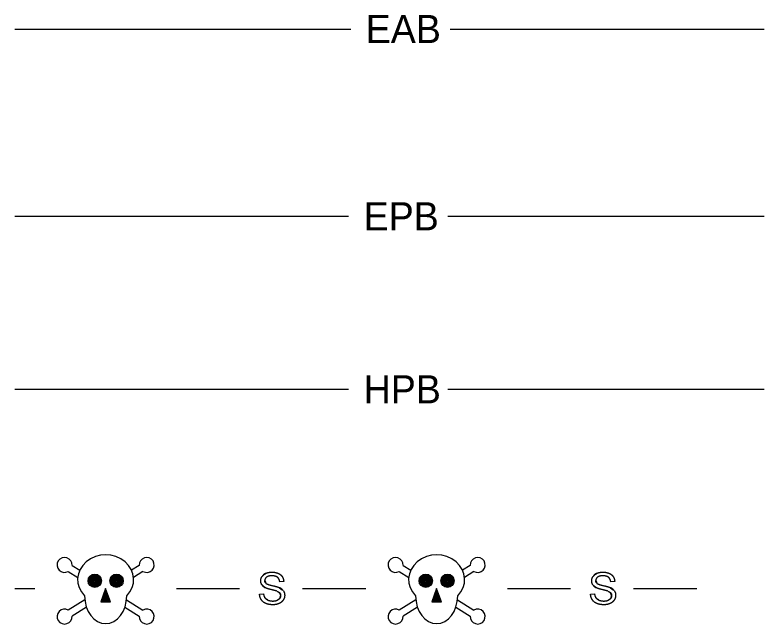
# Model space of a CAD drawing. Extents: x 754056.72 to 754059.56, y 596603.78 to 596605.61.
# Drawn here: x 754057.2575 to 754057.392, y 596604.788 to 596604.8974 of the extents above; entities that cross this region are included whole.
import ezdxf

# ---------------------------------------------------------------- set-up
doc = ezdxf.new("R2010")
doc.units = 0
doc.layers.add('Sheet_Symbology', color=7, linetype='Continuous')

msp = doc.modelspace()

# ---------------------------------------------------------------- linework, layer by layer
at = {"layer": 'Sheet_Symbology'}
for p, q in [((754057.2574689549, 596604.8949028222), (754057.3177740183, 596604.8949028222)), ((754057.3355985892, 596604.8949028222), (754057.3919940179, 596604.8949028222)), ((754057.2574689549, 596604.8612715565), (754057.3173956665, 596604.8612715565)), ((754057.3352202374, 596604.8612715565), (754057.3919940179, 596604.8612715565)), ((754057.2574689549, 596604.8302076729), (754057.3173956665, 596604.8302076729)), ((754057.3352202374, 596604.8302076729), (754057.3919940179, 596604.8302076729)), ((754057.2677177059, 596604.7985606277), (754057.2690904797, 596604.7976978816)), ((754057.2797889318, 596604.7985606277), (754057.2784161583, 596604.7976978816)), ((754057.3271609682, 596604.7985606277), (754057.3285337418, 596604.7976978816)), ((754057.3392321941, 596604.7985606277), (754057.3378594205, 596604.7976978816)), ((754057.2670463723, 596604.7974924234), (754057.2687421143, 596604.7964267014)), ((754057.2804602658, 596604.7974924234), (754057.2787645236, 596604.7964267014)), ((754057.3264896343, 596604.7974924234), (754057.3281853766, 596604.7964267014)), ((754057.3399035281, 596604.7974924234), (754057.3382077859, 596604.7964267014)), ((754057.3057381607, 596604.7956724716), (754057.305021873, 596604.7956163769)), ((754057.365181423, 596604.7956724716), (754057.3644651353, 596604.7956163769)), ((754057.2574689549, 596604.7944340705), (754057.261015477, 596604.7944340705)), ((754057.2864911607, 596604.7944340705), (754057.297813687, 596604.7944340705)), ((754057.3091362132, 596604.7944340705), (754057.3204587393, 596604.7944340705)), ((754057.3459344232, 596604.7944340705), (754057.3572569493, 596604.7944340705)), ((754057.3685794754, 596604.7944340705), (754057.3799020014, 596604.7944340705)), ((754057.273753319, 596604.794022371), (754057.273753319, 596604.794022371)), ((754057.3013972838, 596604.7934243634), (754057.3021049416, 596604.7934847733)), ((754057.3331965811, 596604.794022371), (754057.3331965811, 596604.794022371)), ((754057.3608405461, 596604.7934243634), (754057.3615482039, 596604.7934847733)), ((754057.2700067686, 596604.7924128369), (754057.2670463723, 596604.7905523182)), ((754057.2774998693, 596604.7924128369), (754057.2804602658, 596604.7905523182)), ((754057.3294500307, 596604.7924128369), (754057.3264896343, 596604.7905523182)), ((754057.3369431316, 596604.7924128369), (754057.3399035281, 596604.7905523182)), ((754057.2702921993, 596604.7911021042), (754057.2677177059, 596604.7894841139)), ((754057.2772144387, 596604.7911021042), (754057.2797889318, 596604.7894841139)), ((754057.3297354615, 596604.7911021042), (754057.3271609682, 596604.7894841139)), ((754057.3366577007, 596604.7911021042), (754057.3392321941, 596604.7894841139))]:
    msp.add_line(p, q, dxfattribs=at)
for points in [[(754057.273753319, 596604.7944340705), (754057.2728663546, 596604.7920112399), (754057.2746402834, 596604.7920112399)], [(754057.3331965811, 596604.7944340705), (754057.3323096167, 596604.7920112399), (754057.3340835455, 596604.7920112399)], [(754057.273753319, 596604.794022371), (754057.2730688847, 596604.7921527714), (754057.2744377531, 596604.7921527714)], [(754057.273753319, 596604.7936106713), (754057.273271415, 596604.792294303), (754057.2742352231, 596604.792294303)], [(754057.273753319, 596604.7931989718), (754057.2734739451, 596604.7924358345), (754057.2740326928, 596604.7924358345)], [(754057.3331965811, 596604.794022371), (754057.332512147, 596604.7921527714), (754057.3338810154, 596604.7921527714)], [(754057.3331965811, 596604.7936106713), (754057.3327146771, 596604.792294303), (754057.3336784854, 596604.792294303)], [(754057.3331965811, 596604.7931989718), (754057.3329172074, 596604.7924358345), (754057.3334759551, 596604.7924358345)], [(754057.273753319, 596604.7927872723), (754057.2736764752, 596604.7925773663), (754057.2738301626, 596604.7925773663)], [(754057.3331965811, 596604.7927872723), (754057.3331197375, 596604.7925773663), (754057.3332734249, 596604.7925773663)]]:
    msp.add_lwpolyline(points, close=True, dxfattribs=at)
for centre, radius in [((754057.2718028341, 596604.7958118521), 0.0012001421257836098), ((754057.2757038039, 596604.7958118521), 0.0012001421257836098), ((754057.3312460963, 596604.7958118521), 0.0012001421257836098), ((754057.3351470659, 596604.7958118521), 0.0012001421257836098), ((754057.2718028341, 596604.7958118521), 0.0010586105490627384), ((754057.2718028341, 596604.7958118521), 0.0009170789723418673), ((754057.2718028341, 596604.7958118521), 0.0007755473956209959), ((754057.2718028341, 596604.7958118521), 0.0006340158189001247), ((754057.2718028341, 596604.7958118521), 0.0004924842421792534), ((754057.2718028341, 596604.7958118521), 0.00035095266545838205), ((754057.2718028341, 596604.7958118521), 0.00020942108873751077), ((754057.2718028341, 596604.7958118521), 6.788951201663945e-05), ((754057.2757038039, 596604.7958118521), 0.0010586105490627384), ((754057.2757038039, 596604.7958118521), 0.0009170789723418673), ((754057.2757038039, 596604.7958118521), 0.0007755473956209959), ((754057.2757038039, 596604.7958118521), 0.0006340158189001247), ((754057.2757038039, 596604.7958118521), 0.0004924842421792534), ((754057.2757038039, 596604.7958118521), 0.00035095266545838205), ((754057.2757038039, 596604.7958118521), 0.00020942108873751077), ((754057.2757038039, 596604.7958118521), 6.788951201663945e-05), ((754057.3312460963, 596604.7958118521), 0.0010586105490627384), ((754057.3312460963, 596604.7958118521), 0.0009170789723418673), ((754057.3312460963, 596604.7958118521), 0.0007755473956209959), ((754057.3312460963, 596604.7958118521), 0.0006340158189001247), ((754057.3312460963, 596604.7958118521), 0.0004924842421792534), ((754057.3312460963, 596604.7958118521), 0.00035095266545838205), ((754057.3312460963, 596604.7958118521), 0.00020942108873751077), ((754057.3312460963, 596604.7958118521), 6.788951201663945e-05), ((754057.3351470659, 596604.7958118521), 0.0010586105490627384), ((754057.3351470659, 596604.7958118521), 0.0009170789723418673), ((754057.3351470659, 596604.7958118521), 0.0007755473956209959), ((754057.3351470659, 596604.7958118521), 0.0006340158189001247), ((754057.3351470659, 596604.7958118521), 0.0004924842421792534), ((754057.3351470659, 596604.7958118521), 0.00035095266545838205), ((754057.3351470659, 596604.7958118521), 0.00020942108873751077), ((754057.3351470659, 596604.7958118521), 6.788951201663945e-05)]:
    msp.add_circle(centre, radius, dxfattribs=at)
for centre, start, end in [((754057.2663794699, 596604.7986566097), 355.8976156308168, 299.8061705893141), ((754057.2811271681, 596604.7986566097), 240.19382941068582, 184.10238436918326), ((754057.3258227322, 596604.7986566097), 355.8976156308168, 299.8061705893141), ((754057.3405704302, 596604.7986566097), 240.19382941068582, 184.10238436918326), ((754057.2663794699, 596604.7893881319), 60.19382941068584, 4.1023843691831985), ((754057.2811271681, 596604.7893881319), 175.89761563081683, 119.80617058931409), ((754057.3258227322, 596604.7893881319), 60.19382941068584, 4.1023843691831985), ((754057.3405704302, 596604.7893881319), 175.89761563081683, 119.80617058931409)]:
    msp.add_arc(centre, 0.0013416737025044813, start, end, dxfattribs=at)
for centre, major_axis, ratio, start_param, end_param in [((754057.273753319, 596604.7960240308), (0.005031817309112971, 0), 0.8850143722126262, 5.564242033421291, 10.143721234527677), ((754057.3331965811, 596604.7960240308), (0.005031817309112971, 0), 0.8850143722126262, 5.564242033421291, 10.143721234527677), ((754057.273753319, 596604.7931432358), (-8.091779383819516e-19, -0.005031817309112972), 0.752542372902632, 4.7227348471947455, 7.843635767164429), ((754057.3331965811, 596604.7931432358), (-8.091779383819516e-19, -0.005031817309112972), 0.752542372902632, 4.7227348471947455, 7.843635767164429)]:
    msp.add_ellipse(centre, major_axis=major_axis, ratio=ratio, start_param=start_param, end_param=end_param, dxfattribs=at)
for points in [[(754057.3018525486, 596604.7966045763), (754057.3020963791, 596604.7969774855), (754057.3025646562, 596604.7971707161)], [(754057.3025646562, 596604.7971707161), (754057.3030329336, 596604.7973639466), (754057.3036056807, 596604.7973639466)], [(754057.3036056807, 596604.7973639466), (754057.3042365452, 596604.7973639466), (754057.3047183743, 596604.7971612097)], [(754057.3047183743, 596604.7971612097), (754057.3052002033, 596604.7969584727), (754057.305459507, 596604.7965645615)], [(754057.3612958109, 596604.7966045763), (754057.3615396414, 596604.7969774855), (754057.3620079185, 596604.7971707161)], [(754057.3620079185, 596604.7971707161), (754057.3624761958, 596604.7973639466), (754057.363048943, 596604.7973639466)], [(754057.363048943, 596604.7973639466), (754057.3636798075, 596604.7973639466), (754057.3641616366, 596604.7971612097)], [(754057.3641616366, 596604.7971612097), (754057.3646434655, 596604.7969584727), (754057.3649027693, 596604.7965645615)], [(754057.3016087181, 596604.7958027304), (754057.3016087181, 596604.796231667), (754057.3018525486, 596604.7966045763)], [(754057.3018076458, 596604.795097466), (754057.3016087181, 596604.7954124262), (754057.3016087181, 596604.7958027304)], [(754057.302641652, 596604.7964544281), (754057.3023293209, 596604.7962051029), (754057.3023293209, 596604.795853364)], [(754057.3023293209, 596604.795853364), (754057.3023293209, 596604.7955480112), (754057.302550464, 596604.7953508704)], [(754057.3036368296, 596604.7967037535), (754057.3029539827, 596604.7967037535), (754057.302641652, 596604.7964544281)], [(754057.3046280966, 596604.7964290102), (754057.3042925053, 596604.7967037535), (754057.3036368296, 596604.7967037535)], [(754057.305021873, 596604.7956163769), (754057.3049636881, 596604.7961542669), (754057.3046280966, 596604.7964290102)], [(754057.305459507, 596604.7965645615), (754057.3057188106, 596604.7961706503), (754057.3057381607, 596604.7956724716)], [(754057.3610519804, 596604.7958027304), (754057.3610519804, 596604.796231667), (754057.3612958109, 596604.7966045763)], [(754057.3612509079, 596604.795097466), (754057.3610519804, 596604.7954124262), (754057.3610519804, 596604.7958027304)], [(754057.362084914, 596604.7964544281), (754057.3617725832, 596604.7962051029), (754057.3617725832, 596604.795853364)], [(754057.3617725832, 596604.795853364), (754057.3617725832, 596604.7955480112), (754057.3619937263, 596604.7953508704)], [(754057.3630800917, 596604.7967037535), (754057.362397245, 596604.7967037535), (754057.362084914, 596604.7964544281)], [(754057.3640713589, 596604.7964290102), (754057.3637357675, 596604.7967037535), (754057.3630800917, 596604.7967037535)], [(754057.3644651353, 596604.7956163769), (754057.3644069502, 596604.7961542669), (754057.3640713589, 596604.7964290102)], [(754057.3649027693, 596604.7965645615), (754057.3651620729, 596604.7961706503), (754057.365181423, 596604.7956724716)], [(754057.3024121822, 596604.7945699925), (754057.3020065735, 596604.7947825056), (754057.3018076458, 596604.795097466)], [(754057.3035087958, 596604.7942163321), (754057.3027250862, 596604.794403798), (754057.3024121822, 596604.7945699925)], [(754057.302550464, 596604.7953508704), (754057.3027677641, 596604.7951537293), (754057.3036853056, 596604.7949469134)], [(754057.3045214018, 596604.7939399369), (754057.3042925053, 596604.7940288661), (754057.3035087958, 596604.7942163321)], [(754057.3036853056, 596604.7949469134), (754057.3046028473, 596604.7947400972), (754057.304942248, 596604.7945856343)], [(754057.304942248, 596604.7945856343), (754057.3054359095, 596604.7943578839), (754057.3056711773, 596604.7940084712)], [(754057.3618554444, 596604.7945699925), (754057.3614498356, 596604.7947825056), (754057.3612509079, 596604.795097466)], [(754057.3629520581, 596604.7942163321), (754057.3621683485, 596604.794403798), (754057.3618554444, 596604.7945699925)], [(754057.3619937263, 596604.7953508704), (754057.3622110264, 596604.7951537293), (754057.3631285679, 596604.7949469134)], [(754057.363964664, 596604.7939399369), (754057.3637357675, 596604.7940288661), (754057.3629520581, 596604.7942163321)], [(754057.3631285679, 596604.7949469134), (754057.3640461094, 596604.7947400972), (754057.3643855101, 596604.7945856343)], [(754057.3643855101, 596604.7945856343), (754057.3648791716, 596604.7943578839), (754057.3651144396, 596604.7940084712)], [(754057.3017083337, 596604.7924065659), (754057.3014127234, 596604.7928565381), (754057.3013972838, 596604.7934243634)], [(754057.3021049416, 596604.7934847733), (754057.3021551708, 596604.7930592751), (754057.3023387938, 596604.7927865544)], [(754057.3050320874, 596604.7936057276), (754057.3048783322, 596604.7938046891), (754057.3045214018, 596604.7939399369)], [(754057.3050254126, 596604.7926550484), (754057.3051858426, 596604.7928774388), (754057.3051858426, 596604.793140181)], [(754057.3051858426, 596604.793140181), (754057.3051858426, 596604.7934067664), (754057.3050320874, 596604.7936057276)], [(754057.3059064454, 596604.7932034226), (754057.3059064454, 596604.7927516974), (754057.3056475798, 596604.7923521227)], [(754057.3056711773, 596604.7940084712), (754057.3059064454, 596604.7936590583), (754057.3059064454, 596604.7932034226)], [(754057.361151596, 596604.7924065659), (754057.3608559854, 596604.7928565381), (754057.3608405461, 596604.7934243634)], [(754057.3615482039, 596604.7934847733), (754057.361598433, 596604.7930592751), (754057.3617820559, 596604.7927865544)], [(754057.3644753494, 596604.7936057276), (754057.3643215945, 596604.7938046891), (754057.363964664, 596604.7939399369)], [(754057.3644686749, 596604.7926550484), (754057.3646291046, 596604.7928774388), (754057.3646291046, 596604.793140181)], [(754057.3646291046, 596604.793140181), (754057.3646291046, 596604.7934067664), (754057.3644753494, 596604.7936057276)], [(754057.3653497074, 596604.7932034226), (754057.3653497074, 596604.7927516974), (754057.3650908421, 596604.7923521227)], [(754057.3651144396, 596604.7940084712), (754057.3653497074, 596604.7936590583), (754057.3653497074, 596604.7932034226)], [(754057.3025236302, 596604.7917325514), (754057.3020039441, 596604.7919565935), (754057.3017083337, 596604.7924065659)], [(754057.3023387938, 596604.7927865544), (754057.3025224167, 596604.7925138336), (754057.3029089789, 596604.7923455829)], [(754057.3038121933, 596604.7915085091), (754057.3030433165, 596604.7915085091), (754057.3025236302, 596604.7917325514)], [(754057.3029089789, 596604.7923455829), (754057.303295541, 596604.7921773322), (754057.3037787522, 596604.7921773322)], [(754057.3037787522, 596604.7921773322), (754057.3042078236, 596604.7921773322), (754057.3045364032, 596604.792304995)], [(754057.3049037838, 596604.7917305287), (754057.3044188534, 596604.7915085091), (754057.3038121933, 596604.7915085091)], [(754057.3045364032, 596604.792304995), (754057.3048649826, 596604.792432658), (754057.3050254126, 596604.7926550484)], [(754057.3056475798, 596604.7923521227), (754057.3053887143, 596604.7919525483), (754057.3049037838, 596604.7917305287)], [(754057.3619668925, 596604.7917325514), (754057.3614472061, 596604.7919565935), (754057.361151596, 596604.7924065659)], [(754057.3617820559, 596604.7927865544), (754057.3619656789, 596604.7925138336), (754057.362352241, 596604.7923455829)], [(754057.3632554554, 596604.7915085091), (754057.3624865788, 596604.7915085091), (754057.3619668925, 596604.7917325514)], [(754057.362352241, 596604.7923455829), (754057.3627388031, 596604.7921773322), (754057.3632220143, 596604.7921773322)], [(754057.3632220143, 596604.7921773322), (754057.3636510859, 596604.7921773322), (754057.3639796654, 596604.792304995)], [(754057.3643470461, 596604.7917305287), (754057.3638621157, 596604.7915085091), (754057.3632554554, 596604.7915085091)], [(754057.3639796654, 596604.792304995), (754057.3643082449, 596604.792432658), (754057.3644686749, 596604.7926550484)], [(754057.3650908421, 596604.7923521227), (754057.3648319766, 596604.7919525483), (754057.3643470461, 596604.7917305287)]]:
    msp.add_open_spline(points, degree=2, dxfattribs=at)

# ---------------------------------------------------------------- texts
for s, p in [('EAB', (754057.3204645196, 596604.8923804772)), ('EPB', (754057.3200861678, 596604.8587492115)), ('HPB', (754057.3200861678, 596604.827685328))]:
    msp.add_text(s, height=0.005044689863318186, dxfattribs=at).set_placement(p)

doc.saveas('drawing.dxf')
